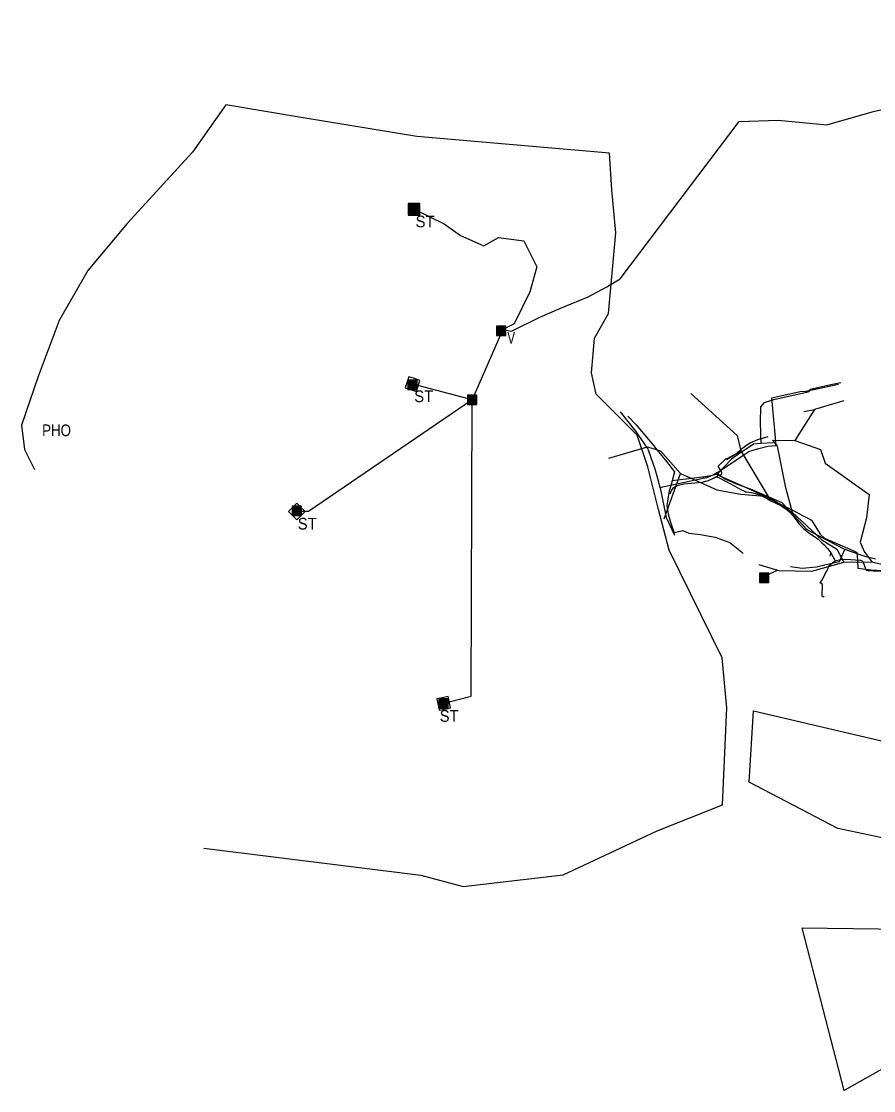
# Model space of a CAD drawing. Extents: x -589836 to -586542, y -1119607 to -1116793.
# Drawn here: x -589836 to -589106, y -1119035 to -1118119 of the extents above; entities that cross this region are included whole.
import ezdxf

# ---------------------------------------------------------------- set-up
doc = ezdxf.new("R2010")
doc.units = 0
doc.header["$LTSCALE"] = 4
for name, color, linetype, lineweight in [('17', 7, 'Continuous', 25), ('18', 7, 'Continuous', 25), ('26', 7, 'Continuous', 25), ('31', 7, 'Continuous', 25), ('39', 7, 'Continuous', 25), ('41', 7, 'Continuous', 25), ('45', 7, 'Continuous', 25), ('49', 7, 'Continuous', 25), ('53', 7, 'Continuous', 25)]:
    doc.layers.add(name, color=color, linetype=linetype, lineweight=lineweight)

msp = doc.modelspace()

# ---------------------------------------------------------------- hatches: boundary and pattern name
at = {"layer": '39'}
msp.add_hatch(color=256, dxfattribs=at).paths.add_polyline_path([(-589203.967, -1118599.607), (-589195.967, -1118599.607), (-589195.967, -1118591.607), (-589203.967, -1118591.607)])
at = {"layer": '49'}
for points in [[(-589503.759, -1118283.658), (-589495.759, -1118283.658), (-589495.759, -1118275.658), (-589503.759, -1118275.658)], [(-589429.243, -1118387.978), (-589421.243, -1118387.978), (-589421.243, -1118379.978), (-589429.243, -1118379.978)], [(-589505.367, -1118434.372), (-589497.367, -1118434.372), (-589497.367, -1118426.372), (-589505.367, -1118426.372)], [(-589454.15, -1118447.17), (-589446.15, -1118447.17), (-589446.15, -1118439.17), (-589454.15, -1118439.17)], [(-589604.261, -1118542.136), (-589596.261, -1118542.136), (-589596.261, -1118534.136), (-589604.261, -1118534.136)], [(-589478.694, -1118707.188), (-589470.694, -1118707.188), (-589470.694, -1118699.188), (-589478.694, -1118699.188)]]:
    msp.add_hatch(color=256, dxfattribs=at).paths.add_polyline_path(points)

# ---------------------------------------------------------------- linework, layer by layer
at = {"layer": '17'}
msp.add_lwpolyline([(-589679.984, -1118827.058), (-589494.095, -1118850.094), (-589457.743, -1118859.906), (-589372.154, -1118849.964), (-589291.675, -1118812.211), (-589235.855, -1118790.07), (-589232.052, -1118706.948), (-589235.996, -1118664.093), (-589281.555, -1118571.935), (-589290.686, -1118536.881), (-589299.818, -1118500.527), (-589308.94, -1118473.264), (-589344.045, -1118438.238), (-589347.961, -1118420.06), (-589345.398, -1118390.187), (-589333.4, -1118369.23), (-589327.139, -1118300.021), (-589330.448, -1118263.305), (-589332.588, -1118231.728), (-589497.541, -1118217.627), (-589594.993, -1118201.498), (-589661.21, -1118190.538), (-589689.737, -1118230.831), (-589745.514, -1118291.933), (-589779.236, -1118332.231), (-589803.863, -1118375.117), (-589821.991, -1118423.19), (-589836.23, -1118464.766), (-589833.609, -1118485.541), (-589824.952, -1118502.808)], dxfattribs=at)
for points in [[(-589494.904, -1118274.801), (-589500.831, -1118274.801), (-589504.904, -1118274.801), (-589504.904, -1118279.658), (-589504.904, -1118284.801), (-589501.367, -1118284.801), (-589498.955, -1118284.801), (-589494.904, -1118284.801), (-589494.904, -1118280.194), (-589494.904, -1118279.658)], [(-589499.467, -1118424.951), (-589504.376, -1118423.344), (-589507.487, -1118432.848), (-589497.983, -1118435.959), (-589494.872, -1118426.455)], [(-589448.428, -1118444.625), (-589451.428, -1118444.625), (-589451.428, -1118441.625), (-589448.428, -1118441.625)], [(-589597.408, -1118534.671), (-589600.36, -1118531.737), (-589607.409, -1118538.83), (-589600.316, -1118545.879), (-589593.267, -1118538.786)], [(-589469.844, -1118701.398), (-589470.733, -1118697.138), (-589475.853, -1118698.206), (-589480.523, -1118699.181), (-589478.48, -1118708.97), (-589470.691, -1118707.344), (-589468.691, -1118706.927)]]:
    msp.add_lwpolyline(points, close=True, dxfattribs=at)
at = {"layer": '26'}
msp.add_line((-589143.06, -1118574.06), (-589139.24, -1118580.96), dxfattribs=at)
for points in [[(-589223.78, -1118489.14), (-589219.55, -1118485.19), (-589215.05, -1118481.76), (-589212.1, -1118479.79), (-589205.63, -1118477.07), (-589196.78, -1118474.42)], [(-589242.88, -1118509.85), (-589241.19, -1118508.85), (-589240.09, -1118508.51), (-589239.35, -1118507.82), (-589238.23, -1118507.51), (-589236.48, -1118506.63), (-589236.32, -1118505.09), (-589239.31, -1118500.39), (-589239.56, -1118500.03), (-589238.78, -1118499.31), (-589232.63, -1118493.45), (-589231.71, -1118493.25), (-589223.78, -1118489.14)], [(-589280.67, -1118523.51), (-589279.2, -1118520.17), (-589277.55, -1118518.22), (-589274.71, -1118516.56), (-589268.8, -1118514.9), (-589259.52, -1118514.11), (-589253.25, -1118513.74), (-589247.68, -1118512.23), (-589242.88, -1118509.85)], [(-589242.88, -1118509.85), (-589240.54, -1118509.03), (-589237.46, -1118510.38), (-589229, -1118515.06), (-589219.41, -1118520.18), (-589216.69, -1118521.24), (-589215.91, -1118521.75), (-589215.15, -1118522), (-589210.91, -1118522.49), (-589207.75, -1118523.26), (-589203.45, -1118524.69), (-589202.55, -1118525), (-589201.67, -1118525.42), (-589200.34, -1118526.08), (-589197.37, -1118527.93), (-589194.32, -1118529.74), (-589189.64, -1118531.96), (-589185.83, -1118533.67), (-589180.31, -1118537.33), (-589178.12, -1118539.31), (-589175.87, -1118541.78), (-589172.76, -1118545.98), (-589171.34, -1118547.92), (-589170.72, -1118548.76), (-589170.03, -1118549.54), (-589169.69, -1118549.94)], [(-589169.69, -1118549.94), (-589166.37, -1118553.16), (-589161.88, -1118556.92), (-589156.86, -1118560.16), (-589153.88, -1118562.39), (-589150.59, -1118565.52), (-589148.68, -1118567.41), (-589145.75, -1118570.38), (-589143.06, -1118574.06)], [(-589143.56, -1118576.92), (-589143.18, -1118575.98), (-589143.06, -1118574.06)], [(-589139.24, -1118580.96), (-589138.02, -1118580.68), (-589134.45, -1118579.85), (-589131.09, -1118579.62), (-589125.95, -1118579.85), (-589122, -1118580.2), (-589117.7, -1118580.35), (-589116.12, -1118581.13), (-589115.05, -1118583.06), (-589113.55, -1118587.12), (-589112.79, -1118588.86), (-589111.32, -1118589.28), (-589110.96, -1118589.24)], [(-589148.84, -1118611.32), (-589149.32, -1118611.9), (-589149.77, -1118611.87), (-589150.24, -1118611.7), (-589150.44, -1118611.23), (-589150.2, -1118601.16), (-589152.55, -1118599.45), (-589151.53, -1118598.84), (-589150.05, -1118596.98), (-589148.15, -1118592.76), (-589146.25, -1118589.28), (-589145.38, -1118587.58), (-589144.63, -1118585.16), (-589142.67, -1118583.44), (-589139.24, -1118580.96)], [(-589110.96, -1118589.24), (-589106.82, -1118589.53), (-589097, -1118589.88)]]:
    msp.add_lwpolyline(points, dxfattribs=at)
at = {"layer": '31'}
for p, q in [((-589262.81, -1118437.73), (-589223.07, -1118473.59)), ((-589157.09, -1118451.31), (-589173.86, -1118478.01)), ((-589166.04, -1118453.19), (-589157.09, -1118451.31)), ((-589131.93, -1118444.04), (-589157.09, -1118451.31)), ((-589223.07, -1118473.59), (-589220.17, -1118486.66)), ((-589193.03, -1118477.62), (-589188.81, -1118482.88)), ((-589193.03, -1118477.62), (-589173.86, -1118478.01)), ((-589173.86, -1118478.01), (-589151.94, -1118485.66)), ((-589333.17, -1118493.13), (-589300.09, -1118483.32)), ((-589232.222, -1118494.246), (-589220.17, -1118486.66)), ((-589220.17, -1118486.66), (-589196.527, -1118525.758)), ((-589151.94, -1118485.66), (-589147.76, -1118497.2)), ((-589147.76, -1118497.2), (-589110.15, -1118524.19)), ((-589285.86, -1118544.92), (-589271.85, -1118506.33)), ((-589271.85, -1118506.33), (-589240.68, -1118520.25)), ((-589187.91, -1118589.16), (-589159.14, -1118589.95)), ((-589159.14, -1118589.95), (-589131.75, -1118582.09))]:
    msp.add_line(p, q, dxfattribs=at)
for points in [[(-589300.09, -1118483.32), (-589288.768, -1118486.702), (-589271.85, -1118506.33)], [(-589188.81, -1118482.88), (-589181.99, -1118517.097), (-589176.186, -1118539.179)], [(-589240.68, -1118520.25), (-589219.999, -1118523.877), (-589196.527, -1118525.758)], [(-589196.527, -1118525.758), (-589176.186, -1118539.179), (-589150.67, -1118563.09)], [(-589110.15, -1118524.19), (-589112.476, -1118544.211), (-589117.79, -1118564.906), (-589114.364, -1118573.017), (-589107.925, -1118581.736)], [(-589150.67, -1118563.09), (-589137.961, -1118570.933), (-589131.75, -1118582.09)], [(-589204.61, -1118584.06), (-589188.681, -1118588.931), (-589187.91, -1118589.16)], [(-589199.838, -1118595.601), (-589199.78, -1118594.25), (-589188.681, -1118588.931)], [(-589131.75, -1118582.09), (-589107.925, -1118581.736), (-589081.97, -1118588.17)]]:
    msp.add_lwpolyline(points, dxfattribs=at)
at = {"layer": '39'}
msp.add_lwpolyline([(-589203.967, -1118599.607), (-589195.967, -1118599.607), (-589195.967, -1118591.607), (-589203.967, -1118591.607)], close=True, dxfattribs=at)
at = {"layer": '41'}
for points in [[(-589423.803, -1118382.943), (-589416.6, -1118384.27), (-589392.15, -1118372.23), (-589375.08, -1118364.91), (-589350.82, -1118354.77), (-589334.88, -1118346.32), (-589323.33, -1118339.43), (-589221.4, -1118204.77), (-589188.05, -1118203.63), (-589146.37, -1118207.65), (-589107.53, -1118196.43), (-589071.34, -1118187.97), (-589022.64, -1118173.8), (-589016.193, -1118171.48), (-588946.566, -1118145.726), (-588943.705, -1118139.754), (-588930.933, -1118120.28), (-588930.16, -1118118.938)], [(-589499.757, -1118279.825), (-589474.15, -1118292.24), (-589460.16, -1118302.31), (-589440.31, -1118311.15), (-589427.5, -1118304.11), (-589406, -1118306.79), (-589394.76, -1118329.2), (-589400.89, -1118350.5), (-589414.29, -1118378.09), (-589421.52, -1118381.778), (-589423.803, -1118382.943), (-589449.474, -1118441.625), (-589450.15, -1118443.17), (-589501.108, -1118429.715)], [(-589240.152, -1118505.458), (-589235.402, -1118502.214), (-589223.922, -1118494.538), (-589215.028, -1118488.554), (-589213.189, -1118487.403), (-589205.865, -1118484.996), (-589196.931, -1118482.815), (-589190.272, -1118482.193), (-589189.845, -1118481.939), (-589193.59, -1118441.285), (-589169.271, -1118435.811), (-589164.28, -1118435.773), (-589136.41, -1118429.738)], [(-589450.15, -1118443.17), (-589590.45, -1118538.7), (-589600.15, -1118538.742)], [(-589474.722, -1118702.893), (-589469.785, -1118701.681), (-589450.88, -1118697.04), (-589450.155, -1118445.019), (-589450.15, -1118443.17)], [(-589289.174, -1118518.355), (-589290.339, -1118513.5), (-589293.303, -1118502.435), (-589298.769, -1118487.182), (-589299.591, -1118484.849), (-589309.979, -1118470.022), (-589323.02, -1118453.313)], [(-589104.858, -1118579.617), (-589112.798, -1118577.57), (-589127.062, -1118572.575), (-589131.609, -1118570.898), (-589159.459, -1118556.577), (-589163.616, -1118554.012), (-589184.764, -1118531.414), (-589210.399, -1118520.237), (-589224.471, -1118515.06), (-589233.969, -1118510.765), (-589236.734, -1118508.922), (-589239.148, -1118506.643), (-589239.759, -1118506.066), (-589239.916, -1118505.824), (-589240.152, -1118505.458), (-589243.464, -1118507.385), (-589249.297, -1118509.773), (-589252.238, -1118510.483), (-589264.31, -1118513.042), (-589288.28, -1118518.164), (-589289.174, -1118518.355), (-589283.978, -1118543.962), (-589276.778, -1118558.873)], [(-589177.566, -1118585.916), (-589167.496, -1118587.193), (-589155.136, -1118586.242), (-589136.268, -1118581.678), (-589135.697, -1118581.621), (-589130.868, -1118571.243)]]:
    msp.add_lwpolyline(points, dxfattribs=at)
at = {"layer": '45'}
for points in [[(-589039.453, -1118830.793), (-589137.096, -1118810.136), (-589212.801, -1118770.546), (-589209.36, -1118709.441), (-589077.736, -1118740.424)], [(-589087.629, -1119009.806), (-589131.504, -1119034.764), (-589167.636, -1118895.341), (-589036.872, -1118897.062)]]:
    msp.add_lwpolyline(points, dxfattribs=at)
at = {"layer": '49'}
for points in [[(-589503.759, -1118283.658), (-589495.759, -1118283.658), (-589495.759, -1118275.658), (-589503.759, -1118275.658)], [(-589429.243, -1118387.978), (-589421.243, -1118387.978), (-589421.243, -1118379.978), (-589429.243, -1118379.978)], [(-589505.367, -1118434.372), (-589497.367, -1118434.372), (-589497.367, -1118426.372), (-589505.367, -1118426.372)], [(-589454.15, -1118447.17), (-589446.15, -1118447.17), (-589446.15, -1118439.17), (-589454.15, -1118439.17)], [(-589604.261, -1118542.136), (-589596.261, -1118542.136), (-589596.261, -1118534.136), (-589604.261, -1118534.136)], [(-589478.694, -1118707.188), (-589470.694, -1118707.188), (-589470.694, -1118699.188), (-589478.694, -1118699.188)]]:
    msp.add_lwpolyline(points, close=True, dxfattribs=at)
at = {"layer": '53'}
msp.add_line((-589316.81, -1118457.2), (-589316.08, -1118457.96), dxfattribs=at)
for points in [[(-589166.2, -1118436.98), (-589161.44, -1118435.9), (-589160.59, -1118433.98), (-589155.56, -1118432.84), (-589153.38, -1118432.34)], [(-589153.38, -1118432.34), (-589148.19, -1118431.16), (-589142.93, -1118430.09), (-589134.49, -1118428.37)], [(-589202.79, -1118480.62), (-589203.14, -1118462.43), (-589202.85, -1118449.14), (-589199.73, -1118445.45), (-589191.67, -1118442.68), (-589172.72, -1118438.45), (-589166.2, -1118436.98)], [(-589316.08, -1118457.96), (-589310.37, -1118463.88), (-589309.85, -1118464.48)], [(-589309.85, -1118464.48), (-589306.86, -1118467.95), (-589294.59, -1118482.36), (-589293.15, -1118484.36)], [(-589192.42, -1118479.83), (-589192.72, -1118479.85), (-589202.79, -1118480.62)], [(-589293.15, -1118484.36), (-589283.6, -1118495.78), (-589276.9, -1118504.84), (-589278.81, -1118512.37)], [(-589202.79, -1118480.62), (-589209.34, -1118481.07), (-589218.88, -1118487.49), (-589220.99, -1118488.89), (-589228.14, -1118494.01)], [(-589228.14, -1118494.01), (-589228.7, -1118494.41), (-589240.55, -1118507.15)], [(-589240.55, -1118507.15), (-589251.82, -1118509.24), (-589253.23, -1118509.41)], [(-589240.55, -1118507.15), (-589211.83, -1118519.91), (-589208.71, -1118521.44)], [(-589278.81, -1118512.37), (-589281.67, -1118522.56), (-589283.5, -1118533.75), (-589282.22, -1118540.77), (-589280.71, -1118546.94), (-589278.2, -1118553.96)], [(-589253.23, -1118509.41), (-589264.68, -1118510.75), (-589278.81, -1118512.37)], [(-589208.71, -1118521.44), (-589200.96, -1118524.91), (-589195.75, -1118527.51), (-589183.37, -1118533.8), (-589173, -1118539.14), (-589169.91, -1118540.8), (-589167.85, -1118541.87), (-589163.73, -1118544.01)], [(-589163.73, -1118544.01), (-589159.62, -1118546.15), (-589152.21, -1118558.13), (-589148.41, -1118561.57), (-589122.2, -1118573.06)], [(-589278.2, -1118553.96), (-589277.15, -1118556.89), (-589275.71, -1118556.53), (-589269.61, -1118554.98), (-589264.74, -1118557.19), (-589254.68, -1118558.54), (-589250.03, -1118559.28)], [(-589250.03, -1118559.28), (-589241.93, -1118560.58), (-589229.49, -1118565.37), (-589219.53, -1118573.38), (-589217.95, -1118574.65)], [(-589122.2, -1118573.06), (-589120.64, -1118573.75), (-589120.29, -1118580.76), (-589119.88, -1118587.41)], [(-589119.88, -1118587.41), (-589108.52, -1118588.76), (-589094.74, -1118589.53)]]:
    msp.add_lwpolyline(points, dxfattribs=at)

# ---------------------------------------------------------------- texts
at = {"layer": '18', "width": 0.85}
msp.add_text('PHO', height=10, dxfattribs=at).set_placement((-589818.435, -1118474.207))
at = {"layer": '49'}
for s, width, p in [('ST', 0.95, (-589498.585, -1118295.329)), ('V', 0.75, (-589420.12, -1118394.934)), ('ST', 0.95, (-589499.745, -1118445.065)), ('ST', 0.95, (-589599.521, -1118554.176)), ('ST', 0.95, (-589477.975, -1118718.862))]:
    msp.add_text(s, height=10, dxfattribs=dict(at, width=width)).set_placement(p)

doc.saveas('drawing.dxf')
